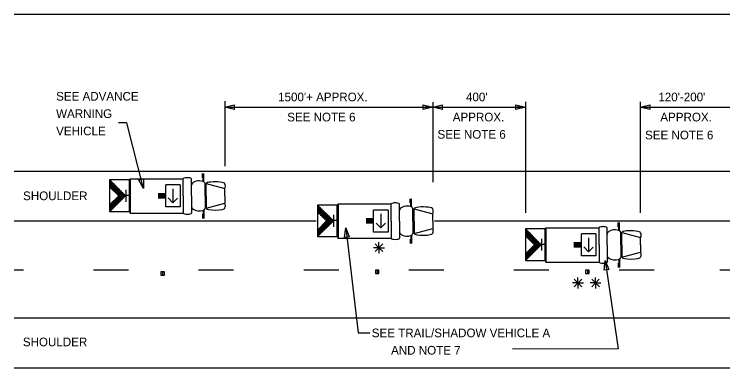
# Model space of a CAD drawing. Extents: x -747 to 834, y -5485 to -3577.
# Drawn here: x -746.8 to -256.3, y -5039.1 to -4794.3 of the extents above; entities that cross this region are included whole.
import ezdxf

# ---------------------------------------------------------------- set-up
doc = ezdxf.new("R2010")
doc.units = 0
doc.layers.add('Level 1', color=7, linetype='Continuous')
doc.layers.add('Working Level 1', color=7, linetype='Continuous')

msp = doc.modelspace()

# ---------------------------------------------------------------- linework, layer by layer
at = {"layer": 'Level 1'}
msp.add_lwpolyline([(-337.84, -4964.83), (-328.65, -5025.88), (-401.93, -5026.16)], dxfattribs=at)
at = {"layer": 'Working Level 1'}
for p, q in [((-746.8, -4794.34), (53.25, -4794.34)), ((-601, -4854.6), (-601, -4899.58)), ((-457.13, -4855.2), (-457.13, -4910.65)), ((-392.99, -4854.96), (-392.99, -4931.85)), ((-313.45, -4854.96), (-313.45, -4931.85)), ((-601, -4858.66), (-595.43, -4858.66)), ((-601, -4858.66), (-457.13, -4858.66)), ((-457.13, -4858.66), (-462.42, -4858.66)), ((-457.13, -4858.66), (-450.95, -4858.66)), ((-457.13, -4858.66), (-392.99, -4858.66)), ((-393.72, -4858.66), (-399, -4858.66)), ((-313.45, -4858.66), (-307.27, -4858.66)), ((-313.45, -4858.66), (-249.31, -4858.66)), ((-746.8, -4902.87), (53.25, -4902.87)), ((-616.49, -4907.53), (-616.49, -4904.62)), ((-616.03, -4910.33), (-616.03, -4904.62)), ((-615.64, -4910.33), (-615.64, -4904.62)), ((-680.72, -4909.02), (-669.76, -4919.96)), ((-666.61, -4908.51), (-666.61, -4932.28)), ((-666.52, -4932.01), (-666.52, -4908.24)), ((-666.52, -4908.24), (-666.52, -4932.01)), ((-666.52, -4908.24), (-629.73, -4908.24)), ((-629.73, -4920.13), (-629.73, -4908.24)), ((-624.09, -4920.13), (-624.09, -4908.24)), ((-680.72, -4913.77), (-674.44, -4920.03)), ((-631.89, -4912.52), (-641.94, -4912.52)), ((-641.94, -4927.74), (-641.94, -4912.52)), ((-631.89, -4912.52), (-631.89, -4927.74)), ((-614.64, -4920.13), (-614.64, -4911.57)), ((-613.86, -4911.57), (-601, -4915.08)), ((-613.86, -4920.13), (-613.86, -4911.57)), ((-669.4, -4924.08), (-669.4, -4915.84)), ((-641.94, -4918.61), (-647.07, -4918.61)), ((-641.94, -4919.37), (-647.07, -4919.37)), ((-636.91, -4915.1), (-636.91, -4924.83)), ((-601, -4920.13), (-601, -4915.08)), ((-680.72, -4926.29), (-674.44, -4920.03)), ((-680.66, -4930.87), (-669.76, -4919.96)), ((-667.1, -4919.77), (-669.46, -4919.77)), ((-641.94, -4920.13), (-647.07, -4920.13)), ((-641.94, -4920.89), (-647.07, -4920.89)), ((-641.94, -4921.65), (-647.07, -4921.65)), ((-636.91, -4924.83), (-640.22, -4921.53)), ((-636.91, -4924.83), (-633.68, -4921.61)), ((-629.73, -4920.13), (-629.73, -4932.01)), ((-624.09, -4920.13), (-624.09, -4932.01)), ((-614.64, -4920.13), (-614.64, -4928.69)), ((-613.86, -4920.13), (-613.86, -4928.69)), ((-601, -4920.13), (-601, -4925.17)), ((-472.63, -4924.94), (-472.63, -4922.03)), ((-472.16, -4927.74), (-472.16, -4922.03)), ((-471.77, -4927.74), (-471.77, -4922.03)), ((-631.89, -4927.74), (-641.94, -4927.74)), ((-613.86, -4928.69), (-601, -4925.17)), ((-536.85, -4926.43), (-525.9, -4937.38)), ((-522.75, -4925.92), (-522.75, -4949.69)), ((-522.65, -4925.65), (-522.65, -4949.42)), ((-522.65, -4949.43), (-522.65, -4925.66)), ((-522.65, -4925.66), (-485.86, -4925.66)), ((-485.86, -4937.54), (-485.86, -4925.66)), ((-480.22, -4937.54), (-480.22, -4925.66)), ((-470.78, -4937.54), (-470.78, -4928.98)), ((-469.99, -4928.98), (-457.13, -4932.5)), ((-469.99, -4937.54), (-469.99, -4928.98)), ((-666.52, -4932.01), (-629.73, -4932.01)), ((-616.49, -4932.72), (-616.49, -4935.63)), ((-616.03, -4929.92), (-616.03, -4935.63)), ((-615.64, -4929.92), (-615.64, -4935.63)), ((-536.85, -4931.18), (-530.57, -4937.44)), ((-525.53, -4941.5), (-525.53, -4933.26)), ((-488.02, -4929.93), (-498.08, -4929.93)), ((-498.08, -4945.15), (-498.08, -4929.93)), ((-493.05, -4932.52), (-493.05, -4942.25)), ((-488.02, -4929.93), (-488.02, -4945.15)), ((-457.13, -4937.54), (-457.13, -4932.5)), ((-746.8, -4937.35), (-600.53, -4937.35)), ((-600.76, -4937.35), (-537.8, -4937.35)), ((-536.85, -4943.71), (-530.57, -4937.44)), ((-536.8, -4948.28), (-525.9, -4937.38)), ((-523.24, -4937.18), (-525.59, -4937.18)), ((-498.08, -4936.02), (-503.2, -4936.02)), ((-498.08, -4936.78), (-503.2, -4936.78)), ((-498.08, -4937.54), (-503.2, -4937.54)), ((-498.08, -4938.3), (-503.2, -4938.3)), ((-498.08, -4939.06), (-503.2, -4939.06)), ((-493.05, -4942.25), (-496.36, -4938.94)), ((-493.05, -4942.25), (-489.82, -4939.02)), ((-485.86, -4937.54), (-485.86, -4949.42)), ((-480.22, -4937.54), (-480.22, -4949.42)), ((-470.78, -4937.54), (-470.78, -4946.1)), ((-469.99, -4937.54), (-469.99, -4946.1)), ((-457.13, -4937.54), (-457.13, -4942.58)), ((-455.82, -4937.35), (53.25, -4937.35)), ((-328.76, -4941.42), (-328.76, -4938.51)), ((-328.3, -4944.22), (-328.3, -4938.51)), ((-327.91, -4944.22), (-327.91, -4938.51)), ((-469.99, -4946.1), (-457.13, -4942.58)), ((-392.99, -4942.91), (-382.03, -4953.85)), ((-378.88, -4942.4), (-378.88, -4966.17)), ((-378.79, -4965.9), (-378.79, -4942.13)), ((-378.79, -4942.13), (-378.79, -4965.9)), ((-378.79, -4942.13), (-341.99, -4942.13)), ((-341.99, -4954.02), (-341.99, -4942.13)), ((-336.36, -4954.02), (-336.36, -4942.13)), ((-488.02, -4945.15), (-498.08, -4945.15)), ((-472.16, -4947.33), (-472.16, -4953.04)), ((-471.77, -4947.33), (-471.77, -4953.04)), ((-392.99, -4947.66), (-386.71, -4953.92)), ((-344.15, -4946.41), (-354.21, -4946.41)), ((-354.21, -4961.63), (-354.21, -4946.41)), ((-344.15, -4946.41), (-344.15, -4961.63)), ((-326.91, -4954.02), (-326.91, -4945.46)), ((-326.13, -4945.46), (-313.27, -4948.97)), ((-326.13, -4954.02), (-326.13, -4945.46)), ((-522.65, -4949.42), (-485.86, -4949.42)), ((-494.3, -4955.97), (-496.96, -4953.31)), ((-494.36, -4956.02), (-491.7, -4953.36)), ((-494.3, -4955.97), (-494.3, -4952.21)), ((-472.63, -4950.14), (-472.63, -4953.04)), ((-379.37, -4953.66), (-381.73, -4953.66)), ((-381.66, -4957.98), (-381.66, -4949.73)), ((-354.21, -4952.5), (-359.34, -4952.5)), ((-354.21, -4953.26), (-359.34, -4953.26)), ((-349.18, -4948.99), (-349.18, -4958.72)), ((-313.27, -4954.02), (-313.27, -4948.97)), ((-494.3, -4955.97), (-498.06, -4955.97)), ((-494.3, -4955.97), (-496.96, -4958.63)), ((-494.3, -4955.97), (-491.64, -4958.63)), ((-494.3, -4955.97), (-494.3, -4959.73)), ((-494.3, -4955.97), (-490.54, -4955.97)), ((-392.99, -4960.18), (-386.71, -4953.92)), ((-392.93, -4964.76), (-382.03, -4953.85)), ((-354.21, -4954.02), (-359.34, -4954.02)), ((-354.21, -4954.78), (-359.34, -4954.78)), ((-354.21, -4955.54), (-359.34, -4955.54)), ((-349.18, -4958.72), (-352.49, -4955.42)), ((-349.18, -4958.72), (-345.95, -4955.5)), ((-341.99, -4954.02), (-341.99, -4965.9)), ((-336.36, -4954.02), (-336.36, -4965.9)), ((-326.91, -4954.02), (-326.91, -4962.58)), ((-326.13, -4954.02), (-326.13, -4962.58)), ((-313.27, -4954.02), (-313.27, -4959.06)), ((-344.15, -4961.63), (-354.21, -4961.63)), ((-326.13, -4962.58), (-313.27, -4959.06)), ((-378.79, -4965.9), (-341.99, -4965.9)), ((-328.76, -4966.61), (-328.76, -4969.52)), ((-328.3, -4963.81), (-328.3, -4969.52)), ((-327.91, -4963.81), (-327.91, -4969.52)), ((-645.28, -4972.59), (-645.29, -4975.02)), ((-642.86, -4972.59), (-645.28, -4972.59)), ((-644.07, -4972.59), (-644.07, -4975.02)), ((-642.86, -4975.02), (-642.86, -4972.59)), ((-496.74, -4971.37), (-496.75, -4973.8)), ((-494.32, -4971.37), (-496.74, -4971.37)), ((-495.52, -4971.37), (-495.53, -4973.8)), ((-494.32, -4973.8), (-494.32, -4971.37)), ((-348.84, -4971.37), (-351.27, -4971.37)), ((-351.27, -4971.37), (-351.27, -4973.8)), ((-350.05, -4971.37), (-350.05, -4973.8)), ((-348.84, -4973.8), (-348.84, -4971.37)), ((-645.29, -4975.02), (-642.86, -4975.02)), ((-496.75, -4973.8), (-494.32, -4973.8)), ((-356.58, -4980.33), (-359.24, -4977.67)), ((-356.65, -4980.38), (-353.98, -4977.72)), ((-356.58, -4980.33), (-356.58, -4976.56)), ((-351.27, -4973.8), (-348.84, -4973.8)), ((-344.41, -4980.33), (-347.07, -4977.67)), ((-344.47, -4980.38), (-341.81, -4977.72)), ((-344.41, -4980.33), (-344.41, -4976.56)), ((-356.58, -4980.33), (-360.35, -4980.33)), ((-356.58, -4980.33), (-359.24, -4982.99)), ((-356.58, -4980.33), (-353.92, -4982.99)), ((-356.58, -4980.33), (-356.58, -4984.09)), ((-356.58, -4980.33), (-352.82, -4980.33)), ((-344.41, -4980.33), (-348.17, -4980.33)), ((-344.41, -4980.33), (-347.07, -4982.99)), ((-344.41, -4980.33), (-341.75, -4982.99)), ((-344.41, -4980.33), (-344.41, -4984.09)), ((-344.41, -4980.33), (-340.65, -4980.33)), ((-746.8, -5004.57), (-98.45, -5004.57)), ((-746.8, -5039.06), (-135.33, -5039.06))]:
    msp.add_line(p, q, dxfattribs=at)
for points in [[(-594.51, -4860.29), (-601.01, -4858.66), (-594.51, -4857.04)], [(-463.63, -4857.04), (-457.13, -4858.66), (-463.63, -4860.29)], [(-450.63, -4860.29), (-457.13, -4858.66), (-450.63, -4857.04)], [(-399.49, -4857.04), (-392.99, -4858.66), (-399.49, -4860.29)], [(-306.95, -4860.29), (-313.45, -4858.66), (-306.95, -4857.04)], [(-680.72, -4909.02), (-680.72, -4930.87), (-667.06, -4930.87), (-667.06, -4909.02)], [(-657.32, -4908.3), (-657.3, -4915), (-660.47, -4909.1)], [(-536.85, -4926.43), (-536.85, -4948.28), (-523.2, -4948.28), (-523.2, -4926.43)], [(-518.1, -4948.84), (-517.25, -4942.2), (-514.87, -4948.46)], [(-392.99, -4942.91), (-392.99, -4964.76), (-379.33, -4964.76), (-379.33, -4942.91)], [(-338.48, -4971.5), (-337.84, -4964.83), (-335.27, -4971.02)]]:
    msp.add_lwpolyline(points, close=True, dxfattribs=at)
for points in [[(-657.3, -4915), (-668.83, -4869.56), (-674.6, -4869.56)], [(-680.72, -4909.53), (-674.94, -4919.54)], [(-680.23, -4909.5), (-672.58, -4922.77)], [(-680.72, -4910.39), (-676.08, -4918.43)], [(-680.72, -4911.25), (-677.23, -4917.3)], [(-680.72, -4912.11), (-678.37, -4916.18)], [(-680.72, -4912.98), (-679.51, -4915.05)], [(-680.72, -4913.84), (-680.66, -4913.93)], [(-679.06, -4910.68), (-672.26, -4922.45)], [(-677.89, -4911.84), (-671.94, -4922.13)], [(-676.71, -4913.03), (-671.63, -4921.83)], [(-675.54, -4914.2), (-671.32, -4921.51)], [(-674.36, -4915.38), (-670.99, -4921.21)], [(-673.19, -4916.55), (-670.67, -4920.91)], [(-672.01, -4917.71), (-670.38, -4920.55)], [(-670.92, -4918.78), (-670.08, -4920.25)], [(-678.68, -4924.26), (-677, -4927.17)], [(-678.36, -4923.94), (-676.68, -4926.86)], [(-678.04, -4923.63), (-676.37, -4926.54)], [(-677.73, -4923.31), (-676.05, -4926.23)], [(-677.42, -4922.99), (-675.74, -4925.91)], [(-677.11, -4922.68), (-675.42, -4925.6)], [(-676.79, -4922.37), (-675.1, -4925.29)], [(-676.47, -4922.05), (-674.79, -4924.97)], [(-676.16, -4921.74), (-674.47, -4924.65)], [(-675.84, -4921.42), (-674.15, -4924.34)], [(-675.53, -4921.11), (-673.84, -4924.02)], [(-675.21, -4920.8), (-673.53, -4923.71)], [(-674.9, -4920.47), (-673.2, -4923.39)], [(-674.58, -4920.16), (-672.89, -4923.08)], [(-680.72, -4926.76), (-679.21, -4929.37)], [(-680.72, -4927.62), (-679.53, -4929.69)], [(-680.72, -4928.48), (-679.84, -4930)], [(-680.57, -4926.15), (-678.9, -4929.05)], [(-680.25, -4925.83), (-678.58, -4928.74)], [(-679.94, -4925.52), (-678.27, -4928.43)], [(-679.62, -4925.2), (-677.95, -4928.12)], [(-679.31, -4924.89), (-677.63, -4927.79)], [(-679, -4924.57), (-677.32, -4927.49)], [(-536.85, -4926.94), (-531.07, -4936.95)], [(-536.85, -4927.8), (-532.22, -4935.84)], [(-536.85, -4928.66), (-533.36, -4934.72)], [(-536.36, -4926.91), (-528.72, -4940.18)], [(-535.2, -4928.09), (-528.4, -4939.87)], [(-534.02, -4929.26), (-528.08, -4939.55)], [(-680.72, -4929.35), (-680.16, -4930.31)], [(-680.72, -4930.21), (-680.48, -4930.62)], [(-536.85, -4929.53), (-534.51, -4933.59)], [(-536.85, -4930.39), (-535.65, -4932.47)], [(-536.85, -4931.25), (-536.8, -4931.34)], [(-532.85, -4930.44), (-527.76, -4939.24)], [(-531.67, -4931.61), (-527.45, -4938.92)], [(-530.5, -4932.79), (-527.12, -4938.63)], [(-529.32, -4933.96), (-526.8, -4938.33)], [(-531.97, -4938.83), (-530.29, -4941.75)], [(-531.66, -4938.52), (-529.97, -4941.43)], [(-531.34, -4938.21), (-529.66, -4941.12)], [(-531.03, -4937.89), (-529.34, -4940.81)], [(-530.71, -4937.57), (-529.02, -4940.49)], [(-528.14, -4935.12), (-526.51, -4937.96)], [(-527.06, -4936.2), (-526.22, -4937.66)], [(-536.71, -4943.56), (-535.03, -4946.46)], [(-536.39, -4943.24), (-534.71, -4946.16)], [(-536.08, -4942.93), (-534.4, -4945.84)], [(-535.76, -4942.61), (-534.08, -4945.53)], [(-535.45, -4942.3), (-533.77, -4945.21)], [(-535.13, -4941.99), (-533.45, -4944.9)], [(-534.82, -4941.67), (-533.14, -4944.58)], [(-534.5, -4941.35), (-532.82, -4944.27)], [(-534.18, -4941.04), (-532.5, -4943.96)], [(-533.87, -4940.72), (-532.18, -4943.64)], [(-533.55, -4940.4), (-531.87, -4943.32)], [(-533.24, -4940.1), (-531.56, -4943.01)], [(-532.92, -4939.78), (-531.23, -4942.7)], [(-532.61, -4939.46), (-530.93, -4942.38)], [(-532.29, -4939.15), (-530.61, -4942.07)], [(-517.25, -4942.2), (-508.63, -5014.79), (-500.72, -5014.79)], [(-392.99, -4943.42), (-387.21, -4953.43)], [(-392.5, -4943.39), (-384.85, -4956.66)], [(-536.85, -4944.17), (-535.35, -4946.78)], [(-536.85, -4945.03), (-535.66, -4947.1)], [(-536.85, -4945.89), (-535.98, -4947.41)], [(-536.85, -4946.76), (-536.29, -4947.72)], [(-536.85, -4947.62), (-536.61, -4948.03)], [(-392.99, -4944.28), (-388.35, -4952.32)], [(-392.99, -4945.14), (-389.49, -4951.19)], [(-392.99, -4946), (-390.64, -4950.07)], [(-392.99, -4946.87), (-391.78, -4948.94)], [(-392.99, -4947.73), (-392.93, -4947.82)], [(-391.33, -4944.57), (-384.53, -4956.34)], [(-390.16, -4945.73), (-384.21, -4956.02)], [(-388.98, -4946.92), (-383.9, -4955.72)], [(-387.81, -4948.09), (-383.59, -4955.4)], [(-386.63, -4949.27), (-383.26, -4955.1)], [(-385.46, -4950.44), (-382.93, -4954.8)], [(-384.28, -4951.6), (-382.64, -4954.44)], [(-383.19, -4952.67), (-382.35, -4954.14)], [(-391.26, -4958.47), (-389.59, -4961.38)], [(-390.95, -4958.15), (-389.27, -4961.06)], [(-390.63, -4957.83), (-388.95, -4960.75)], [(-390.31, -4957.52), (-388.64, -4960.43)], [(-390, -4957.2), (-388.32, -4960.12)], [(-389.69, -4956.88), (-388.01, -4959.8)], [(-389.38, -4956.57), (-387.69, -4959.49)], [(-389.05, -4956.26), (-387.37, -4959.18)], [(-388.74, -4955.94), (-387.06, -4958.86)], [(-388.43, -4955.63), (-386.74, -4958.54)], [(-388.11, -4955.31), (-386.42, -4958.23)], [(-387.79, -4955), (-386.11, -4957.91)], [(-387.48, -4954.69), (-385.8, -4957.6)], [(-387.17, -4954.36), (-385.47, -4957.28)], [(-386.84, -4954.05), (-385.16, -4956.97)], [(-392.99, -4960.65), (-391.48, -4963.26)], [(-392.99, -4961.51), (-391.8, -4963.58)], [(-392.99, -4962.37), (-392.11, -4963.89)], [(-392.99, -4963.24), (-392.42, -4964.2)], [(-392.84, -4960.04), (-391.17, -4962.94)], [(-392.52, -4959.72), (-390.85, -4962.63)], [(-392.21, -4959.41), (-390.54, -4962.32)], [(-391.89, -4959.09), (-390.21, -4962.01)], [(-391.58, -4958.78), (-389.9, -4961.68)], [(-392.99, -4964.1), (-392.75, -4964.51)], [(-746.8, -4971.34), (-740.43, -4971.34)], [(-691.93, -4971.34), (-667.68, -4971.34)], [(-619.18, -4971.34), (-594.93, -4971.34)], [(-546.43, -4971.34), (-522.17, -4971.34)], [(-473.67, -4971.34), (-449.42, -4971.34)], [(-400.92, -4971.34), (-376.66, -4971.34)], [(-328.16, -4971.34), (-303.91, -4971.34)], [(-258.42, -4971.34), (-234.16, -4971.34)]]:
    msp.add_lwpolyline(points, dxfattribs=at)
for centre in [(-604.14, -4913.4), (-604.14, -4926.85), (-460.28, -4930.81), (-460.28, -4944.26), (-316.41, -4947.29), (-316.41, -4960.74)]:
    msp.add_arc(centre, 3.57, 331.8801, 28.1199, dxfattribs=at)
for centre, major_axis, ratio, start_param, end_param in [((-626.91, -4908.24), (2.82, 0), 0.269913, 0, 3.141593), ((-619.37, -4912.15), (4.72, 0.58), 0.503092, 0, 3.141593), ((-607.43, -4911.64), (6.43, -0.07), 0.2034, 0, 3.141593), ((-619.37, -4928.1), (4.72, -0.58), 0.503092, 3.141593, 6.283185), ((-607.43, -4928.61), (6.43, 0.07), 0.2034, 3.141593, 6.283185), ((-483.04, -4925.66), (2.82, 0), 0.269913, 0, 3.141593), ((-475.5, -4929.56), (4.72, 0.58), 0.503092, 0, 3.141593), ((-463.56, -4929.05), (6.43, -0.07), 0.2034, 0, 3.141593), ((-626.91, -4932.01), (2.82, 0), 0.269913, 3.141593, 6.283185), ((-339.18, -4942.13), (2.82, 0), 0.269913, 0, 3.141593), ((-331.64, -4946.04), (4.72, 0.58), 0.503092, 0, 3.141593), ((-475.5, -4945.51), (4.72, -0.58), 0.503092, 3.141593, 6.283185), ((-463.56, -4946.02), (6.43, 0.07), 0.2034, 3.141593, 6.283185), ((-319.7, -4945.53), (6.43, -0.07), 0.2034, 0, 3.141593), ((-483.04, -4949.42), (2.82, 0), 0.269913, 3.141593, 6.283185), ((-331.64, -4961.99), (4.72, -0.58), 0.503092, 3.141593, 6.283185), ((-319.7, -4962.5), (6.43, 0.07), 0.2034, 3.141593, 6.283185), ((-339.18, -4965.9), (2.82, 0), 0.269913, 3.141593, 6.283185)]:
    msp.add_ellipse(centre, major_axis=major_axis, ratio=ratio, start_param=start_param, end_param=end_param, dxfattribs=at)

# ---------------------------------------------------------------- texts
for s, p in [('SEE ADVANCE ', (-717.77, -4854.17)), ("1500'+ APPROX.", (-564.12, -4854.63)), ("400'", (-434.08, -4854.63)), ("120'-200'", (-300.94, -4854.63)), ('WARNING ', (-717.77, -4866.17)), ('SEE NOTE 6', (-557.81, -4868.54)), ('APPROX.', (-443.25, -4868.54)), ('APPROX.', (-299.57, -4868.54)), ('VEHICLE', (-717.77, -4878.17)), ('SEE NOTE 6', (-453.81, -4880.48)), ('SEE NOTE 6', (-310.13, -4880.96)), ('SEE TRAIL/SHADOW VEHICLE A ', (-499.3, -5017.9)), ('      AND NOTE 7', (-499.3, -5029.9))]:
    msp.add_text(s, height=6, dxfattribs=at).set_placement(p)
for p in [(-740.63, -4923.03), (-740.79, -5024.15)]:
    msp.add_text('SHOULDER', height=6, rotation=0, dxfattribs=at).set_placement(p)

doc.saveas('drawing.dxf')
